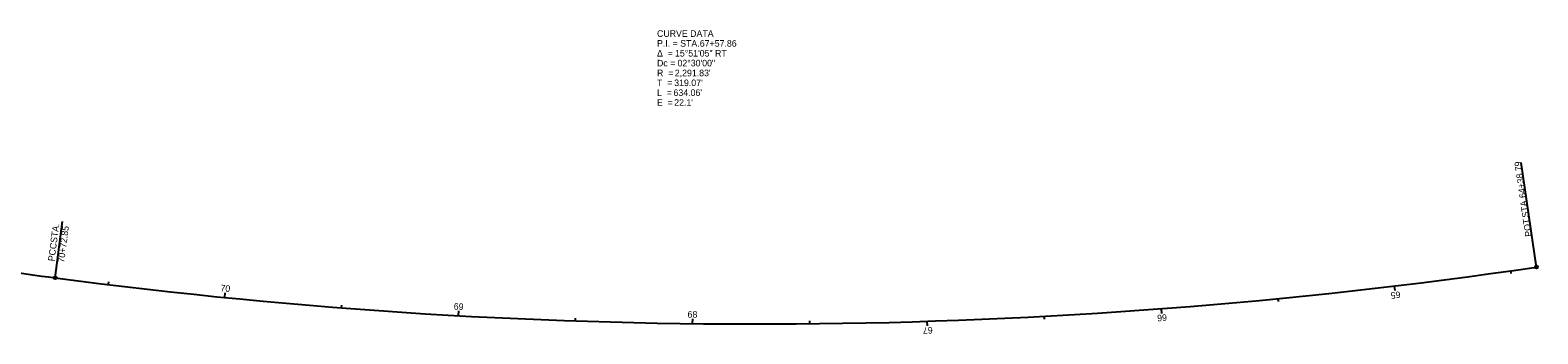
# Model space of a CAD drawing. Extents: x 2203357 to 2204663, y 635542 to 636605.
# Drawn here: x 2204020 to 2204663, y 635542 to 635672 of the extents above; entities that cross this region are included whole.
import ezdxf

# ---------------------------------------------------------------- set-up
doc = ezdxf.new("R2010")
doc.units = 0
for name, color, linetype in [('RW_X_CL', 7, 'Continuous'), ('SH_Border', 7, 'Continuous'), ('SH_Cut_Line', 7, 'Continuous'), ('SH_Data', 7, 'Continuous')]:
    doc.layers.add(name, color=color, linetype=linetype)

msp = doc.modelspace()

# ---------------------------------------------------------------- linework, layer by layer
at = {"layer": 'RW_X_CL'}
for p, q in [((2204651.4, 635568.93), (2204651.57, 635567.74)), ((2204053.14, 635563.04), (2204053.29, 635564.23)), ((2204601.82, 635562.45), (2204602.06, 635560.47)), ((2204102.84, 635557.55), (2204103.03, 635559.54)), ((2204552.11, 635557.06), (2204552.23, 635555.87)), ((2204152.64, 635553.14), (2204152.73, 635554.33)), ((2204202.53, 635549.81), (2204202.64, 635551.81)), ((2204252.48, 635547.58), (2204252.52, 635548.78)), ((2204452.41, 635549.54), (2204452.47, 635548.35)), ((2204502.3, 635552.76), (2204502.45, 635550.77)), ((2204302.46, 635546.43), (2204302.49, 635548.43)), ((2204352.46, 635546.38), (2204352.45, 635547.58)), ((2204402.45, 635547.42), (2204402.51, 635545.42))]:
    msp.add_line(p, q, dxfattribs=at)
at = {"layer": 'SH_Cut_Line'}
for centre, radius, start, end in [((2204217.63, 636986.03), 1432.39, 258.76282, 262.4923), ((2204217.63, 636986.03), 1432.39, 258.76282, 262.4923), ((2204217.63, 636986.03), 1432.39, 258.76282, 262.4923), ((2204329.93, 637838.1), 2291.83, 262.4923, 278.34369), ((2204329.93, 637838.1), 2291.83, 262.4923, 278.34369), ((2204329.93, 637838.1), 2291.83, 262.4923, 278.34369)]:
    msp.add_arc(centre, radius, start, end, dxfattribs=at)
at = {"layer": 'SH_Data'}
for p, q in [((2204662.5, 635570.53), (2204655.97, 635615.05)), ((2204030.48, 635565.92), (2204033.64, 635589.89))]:
    msp.add_line(p, q, dxfattribs=at)
for centre in [(2204662.5, 635570.53), (2204030.48, 635565.92)]:
    msp.add_circle(centre, 0.6, dxfattribs=at)

# ---------------------------------------------------------------- texts
at = {"layer": 'RW_X_CL'}
for s, rotation, p in [('70', 354.31344, (2204100.87, 635560.26)), ('69', 356.81344, (2204200.47, 635552.43)), ('65', 186.81344, (2204604.29, 635560.23)), ('68', 359.31344, (2204300.28, 635548.96)), ('66', 184.31344, (2204504.72, 635550.44)), ('67', 181.81344, (2204404.83, 635544.99))]:
    msp.add_text(s, height=2.8, rotation=rotation, dxfattribs=at).set_placement(p)
at = {"layer": 'SH_Border'}
for s, p in [('CURVE DATA', (2204287.25, 635668.69)), ('P.I. = STA. ', (2204287.25, 635664.49)), ('67+57.86', (2204305.52, 635664.49)), ('Δ  = ', (2204287.25, 635660.29)), ('Dc = ', (2204287.25, 635656.09)), ('15°51\'05" RT', (2204294.93, 635660.29)), ('02°30\'00"', (2204295.99, 635656.09)), ('R  = ', (2204287.25, 635651.89)), ("2,291.83'", (2204294.84, 635651.89)), ('T  = ', (2204287.25, 635647.69)), ('L  = ', (2204287.25, 635643.49)), ("634.06'", (2204294.29, 635643.49)), ("319.07'", (2204294.59, 635647.69)), ('E  = ', (2204287.25, 635639.29)), ("22.1'", (2204294.59, 635639.29))]:
    msp.add_text(s, height=2.8, dxfattribs=at).set_placement(p)
at = {"layer": 'SH_Data'}
for s, rotation, p in [('64+38.79', 98.34369, (2204658.1, 635600.2)), (' STA. ', 98.34369, (2204659.47, 635590.85)), (' STA. ', 82.4923, (2204031.04, 635579.68)), ('70+72.85', 82.4923, (2204034.3, 635572.3)), ('POT', 98.34369, (2204660.52, 635583.72)), ('PCC', 82.4923, (2204030.14, 635572.85))]:
    msp.add_text(s, height=2.8, rotation=rotation, dxfattribs=at).set_placement(p)

doc.saveas('drawing.dxf')
